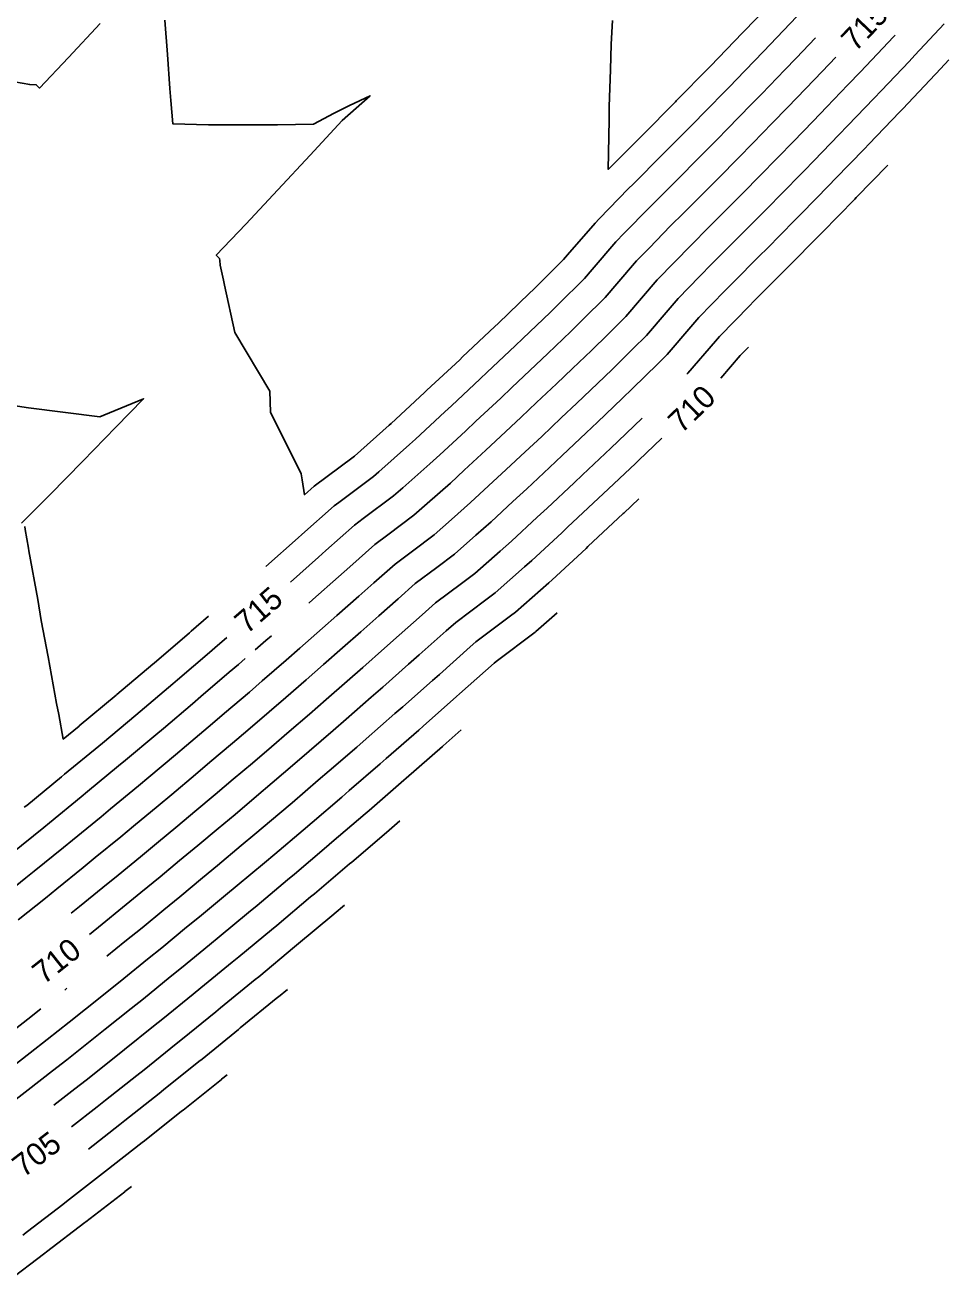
# Model space of a CAD drawing. Extents: x 1487507 to 1489130, y 497211 to 499439.
# Drawn here: x 1488484.6 to 1488583.3, y 498706.5 to 498840.8 of the extents above; entities that cross this region are included whole.
import ezdxf

# ---------------------------------------------------------------- set-up
doc = ezdxf.new("R2010")
doc.units = 0
for name, color, linetype in [('Prop CMT Ditch DDE', 7, 'Continuous'), ('Prop Drainage Ditch Flow Line', 7, 'Continuous'), ('Prop Drainage Structure Pipe Outlet Channel Detail CELL', 7, 'Continuous'), ('Prop Drainage Structure Plot Symbol 20 Scale', 7, 'Continuous')]:
    doc.layers.add(name, color=color, linetype=linetype)

msp = doc.modelspace()

# ---------------------------------------------------------------- linework, layer by layer
at = {"layer": 'Prop CMT Ditch DDE'}
for points in [[(1488564.8, 498843.72), (1488561.42, 498840.19), (1488561.25, 498840.01), (1488557.81, 498836.46), (1488557.68, 498836.32), (1488554.17, 498832.74), (1488554.09, 498832.65), (1488550.52, 498829.05), (1488550.48, 498829), (1488546.89, 498825.42), (1488546.98, 498830.73), (1488546.99, 498832.13), (1488547.13, 498836.06), (1488547.21, 498838.79), (1488547.34, 498841.34)], [(1488582.79, 498840.96), (1488579.66, 498837.62), (1488579.04, 498836.96), (1488576.1, 498833.85), (1488575.29, 498833.01), (1488572.51, 498830.1), (1488571.54, 498829.1), (1488568.91, 498826.37), (1488567.79, 498825.23), (1488565.28, 498822.67), (1488564.08, 498821.46), (1488561.64, 498818.98), (1488560.36, 498817.71), (1488557.97, 498815.31), (1488556.66, 498813.96), (1488554.36, 498811.6), (1488553.09, 498810.13), (1488550.98, 498807.67), (1488549.52, 498806.23), (1488547.3, 498804.03), (1488545.74, 498802.53), (1488543.55, 498800.44), (1488541.88, 498798.86), (1488539.78, 498796.88), (1488538, 498795.21), (1488536, 498793.33), (1488534.1, 498791.58), (1488532.19, 498789.81), (1488530.15, 498788.01), (1488528.3, 498786.37), (1488525.96, 498784.62), (1488524.11, 498783.23), (1488521.86, 498781.23), (1488520.23, 498779.79), (1488517.89, 498777.72), (1488516.35, 498776.36), (1488513.92, 498774.23), (1488512.46, 498772.94), (1488509.91, 498770.74), (1488508.54, 498769.55), (1488505.88, 498767.28), (1488504.6, 498766.19), (1488501.84, 498763.85), (1488500.65, 498762.84), (1488497.78, 498760.44), (1488496.68, 498759.52), (1488493.71, 498757.06), (1488492.69, 498756.22), (1488489.63, 498753.71), (1488488.68, 498752.94), (1488485.53, 498750.39), (1488484.66, 498749.68), (1488481.42, 498747.09)], [(1488483.44, 498834.79), (1488485.08, 498834.49), (1488485.76, 498834.46), (1488485.8, 498834.43), (1488486.13, 498834.11), (1488489.22, 498837.39), (1488492.61, 498841)], [(1488499.49, 498841.37), (1488499.78, 498837.71), (1488500.04, 498834.05), (1488500.16, 498832.78), (1488500.37, 498830.27), (1488504.17, 498830.19), (1488507.89, 498830.19), (1488511.54, 498830.18), (1488515.4, 498830.26), (1488517.59, 498831.44), (1488519.25, 498832.23), (1488521.44, 498833.29), (1488518.47, 498830.63), (1488515.04, 498826.93), (1488511.6, 498823.24), (1488508.15, 498819.56), (1488505, 498816.23), (1488505.03, 498816.2), (1488505.36, 498815.88), (1488505.38, 498815.69), (1488505.43, 498815.19), (1488505.78, 498813.57), (1488505.89, 498813.04), (1488507, 498807.97), (1488510.72, 498801.7), (1488510.81, 498799.48), (1488514.09, 498792.87), (1488514.19, 498792.23), (1488514.43, 498790.64), (1488515.46, 498791.55), (1488515.47, 498791.56), (1488519.62, 498794.66), (1488519.76, 498794.78), (1488523.48, 498798.07), (1488523.68, 498798.25), (1488527.26, 498801.56), (1488527.52, 498801.8), (1488531.02, 498805.07), (1488531.33, 498805.37), (1488534.76, 498808.61), (1488535.12, 498808.96), (1488538.48, 498812.17), (1488538.89, 498812.57), (1488542.13, 498815.78), (1488542.55, 498816.27), (1488545.48, 498819.68), (1488545.92, 498820.13), (1488549.07, 498823.36), (1488549.55, 498823.84), (1488552.71, 498827), (1488553.23, 498827.53), (1488556.33, 498830.66), (1488556.89, 498831.24), (1488559.92, 498834.33), (1488560.55, 498834.98), (1488563.5, 498838.03), (1488564.2, 498838.76), (1488567.06, 498841.75)], [(1488510.3, 498782.98), (1488513.76, 498786.05), (1488514.14, 498786.38), (1488517.62, 498789.47), (1488518.1, 498789.82), (1488521.79, 498792.59), (1488522.36, 498793.09), (1488525.66, 498796), (1488526.29, 498796.59), (1488529.44, 498799.5), (1488530.14, 498800.15), (1488533.21, 498803.02), (1488533.97, 498803.74), (1488536.95, 498806.57), (1488537.78, 498807.35), (1488540.68, 498810.13), (1488541.55, 498810.99), (1488544.34, 498813.75), (1488545.19, 498814.73), (1488547.7, 498817.66), (1488548.6, 498818.59), (1488551.29, 498821.35), (1488552.25, 498822.31), (1488554.94, 498824.99), (1488555.94, 498826.01), (1488558.57, 498828.66), (1488559.62, 498829.73), (1488562.17, 498832.34), (1488563.3, 498833.51), (1488565.75, 498836.05), (1488566.97, 498837.32), (1488569.04, 498839.48)], [(1488577.56, 498839.77), (1488577.39, 498839.59), (1488576.23, 498838.36), (1488573.84, 498835.83), (1488572.51, 498834.44), (1488570.26, 498832.09), (1488568.79, 498830.57), (1488566.66, 498828.36), (1488565.06, 498826.73), (1488563.04, 498824.66), (1488561.37, 498822.97), (1488559.4, 498820.98), (1488557.66, 498819.24), (1488555.75, 498817.32), (1488553.97, 498815.5), (1488552.14, 498813.62), (1488550.46, 498811.66), (1488548.77, 498809.7), (1488546.87, 498807.82), (1488545.09, 498806.06), (1488543.08, 498804.14), (1488541.35, 498802.48), (1488539.24, 498800.49), (1488537.59, 498798.93), (1488535.38, 498796.86), (1488533.81, 498795.39), (1488531.5, 498793.25), (1488530.02, 498791.87), (1488527.55, 498789.7), (1488526.13, 498788.44), (1488523.34, 498786.35), (1488521.95, 498785.31), (1488519.28, 498782.95), (1488518.08, 498781.88), (1488515.33, 498779.45), (1488514.89, 498779.05)], [(1488483.83, 498745.2), (1488486.75, 498747.53), (1488487.96, 498748.51), (1488490.78, 498750.79), (1488492.07, 498751.85), (1488494.8, 498754.08), (1488496.17, 498755.22), (1488498.79, 498757.39), (1488500.26, 498758.61), (1488502.77, 498760.72), (1488504.33, 498762.04), (1488506.73, 498764.07), (1488508.39, 498765.49), (1488510.67, 498767.45), (1488512.43, 498768.97), (1488514.6, 498770.84), (1488516.46, 498772.48), (1488518.5, 498774.26), (1488520.45, 498775.99), (1488522.39, 498777.7), (1488524.43, 498779.52), (1488526.27, 498781.15), (1488528.58, 498782.88), (1488530.47, 498784.3), (1488532.75, 498786.31), (1488534.37, 498787.75), (1488536.71, 498789.91), (1488538.18, 498791.28), (1488540.62, 498793.56), (1488541.97, 498794.83), (1488544.52, 498797.24), (1488545.75, 498798.4), (1488548.39, 498800.93), (1488549.5, 498801.99), (1488552.18, 498804.65), (1488553.19, 498805.64), (1488555.73, 498808.59), (1488556.58, 498809.58), (1488559.34, 498812.42), (1488560.2, 498813.3), (1488563.07, 498816.17), (1488563.87, 498816.97), (1488566.8, 498819.94), (1488567.52, 498820.67), (1488570.51, 498823.73), (1488571.15, 498824.39), (1488574.28, 498827.62), (1488574.76, 498828.12), (1488578.06, 498831.57), (1488578.36, 498831.88), (1488581.84, 498835.56), (1488581.93, 498835.65), (1488583.3, 498837.12)], [(1488576.77, 498825.88), (1488573.4, 498822.4), (1488573.23, 498822.22), (1488569.76, 498818.67), (1488569.51, 498818.42), (1488566.1, 498814.97), (1488565.77, 498814.64), (1488562.42, 498811.29), (1488562.02, 498810.88), (1488558.79, 498807.56), (1488558.36, 498807.05), (1488555.4, 498803.62), (1488555.29, 498803.51)], [(1488479.27, 498800.79), (1488484.93, 498799.94), (1488492.56, 498798.96), (1488492.98, 498799.13), (1488497.23, 498800.9), (1488494.28, 498797.86), (1488490.75, 498794.24), (1488487.2, 498790.63), (1488484.18, 498787.59)], [(1488550.53, 498798.83), (1488547.94, 498796.36), (1488547.16, 498795.61), (1488544.16, 498792.78), (1488543.24, 498791.91), (1488540.37, 498789.22), (1488539.31, 498788.24), (1488536.55, 498785.68), (1488535.35, 498784.62), (1488532.64, 498782.23), (1488531.2, 498781.15), (1488528.44, 498779.07), (1488527, 498777.8), (1488524.54, 498775.62), (1488523, 498774.25), (1488520.65, 498772.17), (1488519.01, 498770.73), (1488516.74, 498768.74), (1488514.96, 498767.2), (1488512.81, 498765.34), (1488510.89, 498763.7), (1488508.86, 498761.95), (1488506.82, 498760.23), (1488504.89, 498758.59), (1488502.73, 498756.79), (1488500.91, 498755.26), (1488498.63, 498753.37), (1488496.9, 498751.94), (1488494.51, 498749.99), (1488492.88, 498748.65), (1488490.38, 498746.63), (1488489.5, 498745.92)], [(1488493.31, 498741.31), (1488495.24, 498742.87), (1488497.08, 498744.36), (1488499.4, 498746.26), (1488501.11, 498747.67), (1488503.54, 498749.68), (1488505.13, 498751), (1488507.67, 498753.13), (1488509.13, 498754.35), (1488511.8, 498756.61), (1488513.11, 498757.72), (1488515.91, 498760.12), (1488517.08, 498761.12), (1488520.01, 498763.66), (1488521.02, 498764.54), (1488524.1, 498767.24), (1488524.95, 498767.98), (1488528.12, 498770.79), (1488528.86, 498771.44), (1488532.15, 498774.37), (1488532.76, 498774.91), (1488536.44, 498777.68), (1488536.98, 498778.08), (1488540.54, 498781.23), (1488540.9, 498781.55), (1488544.52, 498784.91), (1488544.73, 498785.1), (1488548.48, 498788.62), (1488548.55, 498788.68), (1488550.15, 498790.2)], [(1488484.54, 498787.24), (1488484.59, 498786.93), (1488484.76, 498785.92), (1488484.94, 498784.93), (1488484.99, 498784.63), (1488485.92, 498779.45), (1488486.3, 498777.2), (1488487.03, 498773.32), (1488487.93, 498768.33), (1488488.17, 498767.15), (1488488.66, 498764.52), (1488490.34, 498765.91), (1488490.36, 498765.93), (1488494.29, 498769.21), (1488494.37, 498769.28), (1488498.22, 498772.53), (1488498.36, 498772.65), (1488502.13, 498775.88), (1488502.33, 498776.05), (1488504.18, 498777.65)], [(1488482.83, 498729.19), (1488485.12, 498730.99), (1488486.94, 498732.41), (1488489.29, 498734.28), (1488491.04, 498735.66), (1488493.48, 498737.62), (1488495.12, 498738.93), (1488497.67, 498741), (1488499.18, 498742.22), (1488501.84, 498744.4), (1488503.22, 498745.53), (1488506, 498747.84), (1488507.25, 498748.87), (1488510.15, 498751.3), (1488511.25, 498752.23), (1488514.29, 498754.8), (1488515.24, 498755.61), (1488518.41, 498758.33), (1488519.21, 498759.01), (1488522.53, 498761.89), (1488523.16, 498762.44), (1488526.64, 498765.49), (1488527.1, 498765.89), (1488530.67, 498769.06), (1488531.01, 498769.36), (1488534.72, 498772.65), (1488534.93, 498772.83), (1488539.07, 498775.94), (1488539.15, 498776.01), (1488541.42, 498778.02)], [(1488509.17, 498774.06), (1488510.31, 498775.05), (1488510.89, 498775.55)], [(1488508.11, 498773.14), (1488507.38, 498772.51), (1488506.4, 498771.66), (1488503.37, 498769.07), (1488502.48, 498768.3), (1488499.35, 498765.66), (1488498.53, 498764.96), (1488495.31, 498762.27), (1488494.57, 498761.65), (1488491.26, 498758.91), (1488490.58, 498758.35), (1488487.19, 498755.58), (1488486.59, 498755.08), (1488483.1, 498752.27)], [(1488531.18, 498765.51), (1488529.25, 498763.79), (1488529.19, 498763.74), (1488525.31, 498760.34), (1488525.06, 498760.12), (1488521.35, 498756.9), (1488520.92, 498756.54), (1488517.37, 498753.49), (1488516.78, 498752.99), (1488513.37, 498750.1), (1488512.62, 498749.47), (1488509.36, 498746.74), (1488508.46, 498745.99), (1488505.33, 498743.39), (1488504.28, 498742.54), (1488501.28, 498740.07), (1488500.09, 498739.12), (1488497.21, 498736.77), (1488495.9, 498735.73), (1488493.12, 498733.5), (1488491.7, 498732.37), (1488489.02, 498730.25), (1488487.51, 498729.07), (1488484.9, 498727.02), (1488483.31, 498725.79)], [(1488524.62, 498755.78), (1488523.48, 498754.8), (1488523.43, 498754.75), (1488519.5, 498751.38), (1488519.26, 498751.18), (1488515.49, 498747.98), (1488515.09, 498747.65), (1488511.47, 498744.61), (1488510.91, 498744.15), (1488507.43, 498741.26), (1488506.72, 498740.68), (1488503.37, 498737.93), (1488502.52, 498737.24), (1488499.3, 498734.62), (1488498.31, 498733.83), (1488495.2, 498731.34), (1488494.1, 498730.46), (1488491.09, 498728.08), (1488489.9, 498727.15), (1488487.64, 498725.38)], [(1488491.35, 498720.7), (1488494.69, 498723.31), (1488495.25, 498723.75), (1488498.9, 498726.65), (1488499.37, 498727.02), (1488503.14, 498730.05), (1488503.48, 498730.32), (1488507.37, 498733.48), (1488507.57, 498733.64), (1488511.6, 498736.95), (1488511.64, 498736.98), (1488512.6, 498737.77)], [(1488482.73, 498732.91), (1488484.86, 498734.58), (1488486.27, 498735.69)], [(1488506.16, 498728.65), (1488505.57, 498728.17), (1488505.55, 498728.15), (1488501.46, 498724.87), (1488501.3, 498724.74), (1488497.32, 498721.58), (1488497.08, 498721.39), (1488493.17, 498718.33), (1488492.84, 498718.07), (1488489.01, 498715.09), (1488488.59, 498714.78), (1488484.82, 498711.88), (1488484.32, 498711.51)], [(1488482.66, 498706.5), (1488486.69, 498709.56), (1488486.87, 498709.7), (1488490.97, 498712.84), (1488491.07, 498712.91), (1488495.23, 498716.14), (1488495.24, 498716.16), (1488495.93, 498716.69)]]:
    msp.add_lwpolyline(points, dxfattribs=at)
at = {"layer": 'Prop Drainage Ditch Flow Line'}
for points in [[(1488571.22, 498837.42), (1488569.74, 498835.88), (1488568.01, 498834.07), (1488566.05, 498832.04), (1488564.42, 498830.35), (1488562.34, 498828.23), (1488560.8, 498826.66), (1488558.66, 498824.49), (1488557.17, 498822.99), (1488554.96, 498820.77), (1488553.52, 498819.34), (1488551.29, 498817.04), (1488549.92, 498815.64), (1488547.82, 498813.2), (1488546.56, 498811.73), (1488544.21, 498809.4), (1488542.89, 498808.1), (1488540.43, 498805.75), (1488539.15, 498804.52), (1488536.6, 498802.12), (1488535.4, 498800.97), (1488532.76, 498798.5), (1488531.63, 498797.45), (1488528.89, 498794.92), (1488527.84, 498793.94), (1488524.96, 498791.39), (1488523.96, 498790.51), (1488520.72, 498788.09), (1488519.78, 498787.39), (1488516.71, 498784.67), (1488515.92, 498783.96), (1488512.92, 498781.31)], [(1488558.92, 498803.11), (1488561, 498805.52), (1488561.01, 498805.54), (1488561.88, 498806.42)], [(1488491.45, 498743.65), (1488492.81, 498744.75), (1488494.98, 498746.51), (1488496.95, 498748.13), (1488499.01, 498749.8), (1488501.08, 498751.53), (1488503.02, 498753.13), (1488505.2, 498754.96), (1488507.01, 498756.47), (1488509.31, 498758.42), (1488510.99, 498759.84), (1488513.4, 498761.91), (1488514.94, 498763.23), (1488517.48, 498765.43), (1488518.88, 498766.64), (1488521.55, 498768.99), (1488522.8, 498770.07), (1488525.56, 498772.52), (1488526.7, 498773.53), (1488529.57, 498776.08), (1488530.6, 498776.99), (1488533.82, 498779.41), (1488534.81, 498780.16), (1488537.94, 498782.93), (1488538.72, 498783.62), (1488541.92, 498786.58), (1488542.55, 498787.16), (1488545.86, 498790.26), (1488546.36, 498790.73), (1488549.79, 498793.98), (1488550.14, 498794.31), (1488552.62, 498796.68)], [(1488506.14, 498775.39), (1488504.86, 498774.28), (1488504.27, 498773.77), (1488500.86, 498770.86), (1488500.35, 498770.42), (1488496.86, 498767.47), (1488496.41, 498767.09), (1488492.84, 498764.1), (1488492.45, 498763.78), (1488488.8, 498760.76), (1488488.48, 498760.49), (1488484.75, 498757.44), (1488484.49, 498757.23)], [(1488518.7, 498746.78), (1488517.61, 498745.86), (1488517.57, 498745.82), (1488513.58, 498742.48), (1488513.37, 498742.3), (1488509.54, 498739.12), (1488509.16, 498738.81), (1488505.47, 498735.78), (1488504.95, 498735.36), (1488501.39, 498732.47), (1488500.72, 498731.94), (1488497.29, 498729.18), (1488496.5, 498728.56), (1488493.17, 498725.92), (1488492.29, 498725.23), (1488489.53, 498723.07)]]:
    msp.add_lwpolyline(points, dxfattribs=at)
at = {"layer": 'Prop Drainage Structure Plot Symbol 20 Scale'}
msp.add_lwpolyline([(1488489.03, 498737.88), (1488488.95, 498737.82), (1488488.81, 498737.7)], dxfattribs=at)

# ---------------------------------------------------------------- texts
at = {"layer": 'Prop Drainage Structure Pipe Outlet Channel Detail CELL'}
for s, rotation, p in [('715', 46.4965, (1488573.31, 498837.9)), ('710', 44.2461, (1488554.73, 498797.1)), ('715', 40.9845, (1488508.28, 498775.67)), ('710', 38.4641, (1488486.57, 498738.22)), ('705', 37.5468, (1488484.4, 498717.59))]:
    msp.add_text(s, height=2.4, rotation=rotation, dxfattribs=at).set_placement(p)

doc.saveas('drawing.dxf')
